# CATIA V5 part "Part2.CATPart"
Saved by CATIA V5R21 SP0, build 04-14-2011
Part number: Part2
Bounding box of the stored display mesh (mm): x -12.5 to 12.5, y -12.31 to 12.31, z 0 to 5
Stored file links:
  D:\CATIA V5R21 E-RESOURCES\CATIA-V5R21\catia-v5r21-prt\c16-catia-v5r20-prt\Planer Joint-(Fig16-33)\CAT_V5R21_Part2.CATPart
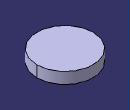
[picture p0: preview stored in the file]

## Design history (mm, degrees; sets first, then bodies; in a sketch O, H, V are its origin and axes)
Body1 (main body)
  Sketch1 on xy-plane, origin (0, 0, 0), H (1, 0, 0), V (0, 1, 0)
    circle A1 centre (0, 0) radius 12.5
    point P1 (0, 12.5)
    radius A1 = 12.5
    coincidence: A1 P1, P1 V
  Pad1: profile Sketch1, direction (0, 0, 1), length 5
